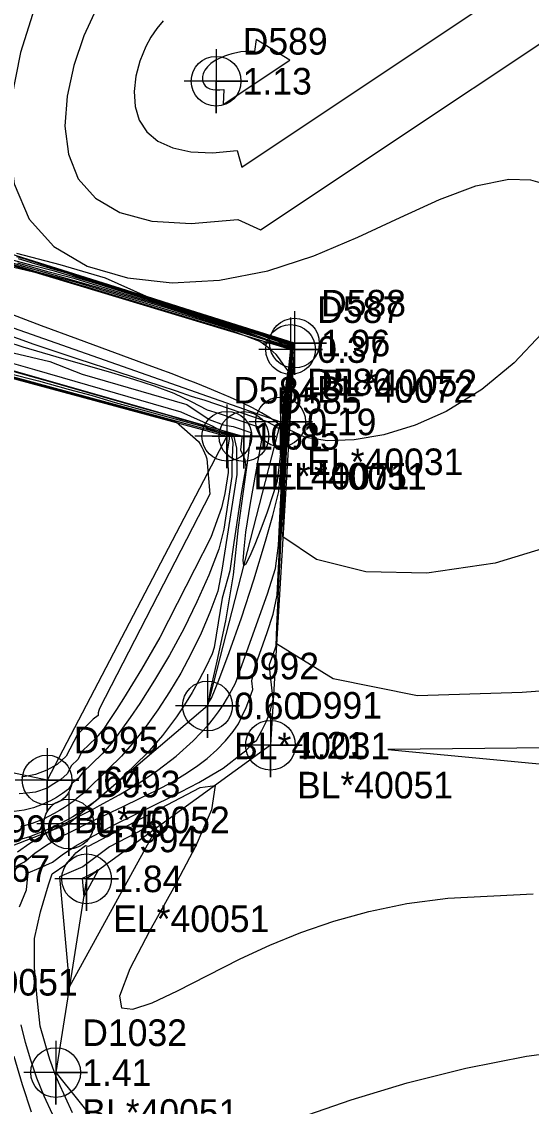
# Model space of a CAD drawing. Extents: x 2356077 to 2359823, y 225951 to 227822.
# Drawn here: x 2357246.2 to 2357294.1, y 226739.1 to 226841 of the extents above; entities that cross this region are included whole.
import ezdxf

# ---------------------------------------------------------------- set-up
doc = ezdxf.new("R2010")
doc.units = 0
for name, color, linetype in [('DTM Contours Major', 7, 'Continuous'), ('DTM Contours Minor', 7, 'Continuous'), ('Exist DTM Breakline', 7, 'Continuous'), ('Exist DTM Breakline Cogo Comment', 7, 'Continuous'), ('Exist DTM Breakline Cogo Elevation', 7, 'Continuous'), ('Exist DTM Breakline Cogo Number', 7, 'Continuous'), ('Exist DTM Breakline Cogo Point CELL', 7, 'Continuous'), ('Exist DTM Breakline Underwater', 7, 'Continuous'), ('Exist DTM Breakline Underwater Cogo Comment', 7, 'Continuous'), ('Exist DTM Breakline Underwater Cogo Elevation', 7, 'Continuous'), ('Exist DTM Breakline Underwater Cogo Number', 7, 'Continuous'), ('Exist DTM Breakline Underwater Cogo Point CELL', 7, 'Continuous'), ('Exist DTM Drainline', 7, 'Continuous'), ('Exist DTM Drainline Cogo Comment', 7, 'Continuous'), ('Exist DTM Drainline Cogo Elevation', 7, 'Continuous'), ('Exist DTM Drainline Cogo Number', 7, 'Continuous'), ('Exist DTM Drainline Cogo Point CELL', 7, 'Continuous'), ('Exist DTM Regular Point CELL', 7, 'Continuous'), ('Exist DTM Regular Point Cogo Elevation', 7, 'Continuous'), ('Exist DTM Regular Point Cogo Number', 7, 'Continuous')]:
    doc.layers.add(name, color=color, linetype=linetype)

msp = doc.modelspace()

# ---------------------------------------------------------------- linework, layer by layer
at = {"layer": 'DTM Contours Major'}
for points in [[(2357245.17, 226761.38), (2357246.44, 226762.04), (2357247.42, 226762.86), (2357248.52, 226763.61), (2357249.71, 226764.31), (2357250.98, 226764.93), (2357252.53, 226765.74), (2357254.12, 226766.49), (2357255.73, 226767.24), (2357257.33, 226768), (2357258.88, 226768.77), (2357260.36, 226769.56), (2357261.53, 226770.26), (2357262.63, 226770.99), (2357263.64, 226771.75), (2357264.55, 226772.55), (2357265.36, 226773.39), (2357266.07, 226774.29), (2357266.57, 226775), (2357266.93, 226775.75), (2357267.29, 226776.54), (2357267.62, 226777.36), (2357267.92, 226778.23), (2357267.82, 226779.05), (2357268.17, 226780.47), (2357269.28, 226783.58), (2357269.83, 226785.32), (2357270.21, 226787.1), (2357271.18, 226806.65), (2357271.23, 226807.34), (2357271.3, 226807.88), (2357271.36, 226808.56), (2357271.53, 226809.81), (2357271.53, 226810.41), (2357269.32, 226811.1), (2357267.47, 226811.77), (2357259.34, 226814.34), (2357256.62, 226815.18), (2357251.21, 226816.82), (2357248.64, 226817.5), (2357245.83, 226818.3)], [(2357245.43, 226808.13), (2357249.14, 226807.08), (2357256.93, 226804.85), (2357260.08, 226803.98), (2357261.05, 226803.68), (2357262.02, 226803.42), (2357263, 226803.14), (2357263.66, 226802.84), (2357266.11, 226802.14), (2357266.39, 226800.92), (2357266.41, 226798.45), (2357265.01, 226789.44), (2357264.64, 226787.46), (2357263.89, 226785.46), (2357263.05, 226783.51), (2357262.13, 226781.61), (2357261.15, 226779.77), (2357260.1, 226778.01), (2357259, 226776.33), (2357257.89, 226774.77), (2357256.74, 226773.31), (2357255.58, 226771.95), (2357254.33, 226770.73), (2357252.05, 226768.53), (2357251.6, 226768.16), (2357251.14, 226767.8), (2357250.67, 226767.46), (2357250.2, 226767.14), (2357249.73, 226766.84), (2357249.24, 226766.56), (2357248.23, 226766.05), (2357247.17, 226765.64), (2357246.06, 226765.31)], [(2357247.12, 226738.51), (2357246.25, 226741.06), (2357245.46, 226743.74)]]:
    msp.add_lwpolyline(points, dxfattribs=at)
at = {"layer": 'DTM Contours Minor'}
for points in [[(2357253.23, 226842.23), (2357252.04, 226839.67), (2357251.08, 226836.88), (2357250.45, 226834), (2357250.25, 226831.18), (2357250.57, 226828.54), (2357251.51, 226826.24), (2357253.12, 226824.4), (2357255.42, 226823.06), (2357258.42, 226822.25), (2357262.11, 226822.02), (2357266.5, 226822.4), (2357268.65, 226821.44), (2357308.56, 226848.03)], [(2357247.4, 226842.27), (2357246.07, 226838.09), (2357245.22, 226833.8), (2357244.97, 226829.61), (2357245.48, 226825.75), (2357246.87, 226822.43), (2357249.2, 226819.87), (2357252.35, 226818.03), (2357256.12, 226816.91), (2357260.33, 226816.46), (2357264.8, 226816.69), (2357269.34, 226817.57), (2357273.65, 226818.98), (2357277.81, 226820.74), (2357281.77, 226822.59), (2357285.48, 226824.29), (2357288.91, 226825.58), (2357292, 226826.21), (2357294.03, 226826.14), (2357295.8, 226825.63)], [(2357259.5, 226841.09), (2357258.89, 226840.35), (2357258.34, 226839.53), (2357257.85, 226838.65), (2357257.3, 226837.29), (2357256.92, 226835.87), (2357256.76, 226834.42), (2357256.85, 226833.03), (2357257.23, 226831.75), (2357257.94, 226830.63), (2357258.99, 226829.76), (2357260.39, 226829.13), (2357262.1, 226828.76), (2357264.13, 226828.68), (2357266.44, 226828.89), (2357266.89, 226827.32), (2357289.98, 226842.71)], [(2357271.4, 226837.39), (2357268.24, 226839.32), (2357268.09, 226838.2), (2357267.67, 226838.22), (2357267.24, 226838.2), (2357266.81, 226838.15), (2357266.38, 226838.07), (2357265.96, 226837.97), (2357265.55, 226837.85), (2357265.25, 226837.75), (2357264.97, 226837.63), (2357264.69, 226837.51), (2357264.44, 226837.37), (2357264.2, 226837.22), (2357263.98, 226837.07), (2357263.81, 226836.92), (2357263.66, 226836.76), (2357263.52, 226836.6), (2357263.41, 226836.43), (2357263.32, 226836.26), (2357263.25, 226836.09), (2357263.19, 226835.84), (2357263.18, 226835.6), (2357263.22, 226835.37), (2357263.31, 226835.16), (2357263.44, 226834.97), (2357263.63, 226834.82), (2357263.87, 226834.7), (2357264.15, 226834.62), (2357264.47, 226834.58), (2357264.82, 226834.58), (2357265.21, 226834.63), (2357265.13, 226833.21), (2357271.4, 226837.39)], [(2357245.38, 226809.88), (2357248.82, 226809.06), (2357251.86, 226807.87), (2357261.73, 226805.02), (2357263.81, 226803.61), (2357265.16, 226803.11), (2357266.06, 226802.95), (2357267.74, 226802.38), (2357267.5, 226800.22), (2357266.54, 226793.47), (2357266.09, 226789.02), (2357265.34, 226784.67), (2357264.54, 226780.88), (2357263.92, 226778.14), (2357263.72, 226776.93), (2357264.04, 226777.4), (2357264.74, 226779.09), (2357265.71, 226781.71), (2357266.85, 226784.97), (2357268.02, 226788.55), (2357269.13, 226792.18), (2357269.8, 226794.57), (2357270.38, 226796.84), (2357270.65, 226800.1), (2357270.89, 226805.05), (2357270.97, 226805.95), (2357271.31, 226808.43), (2357271.49, 226810.24), (2357269.76, 226810.78), (2357269.08, 226811.08), (2357266.93, 226811.76), (2357262.96, 226812.98), (2357251.25, 226816.51), (2357247.66, 226817.45), (2357242.79, 226818.92)], [(2357245.78, 226762.97), (2357246.95, 226763.8), (2357248.22, 226764.56), (2357249.56, 226765.28), (2357250.85, 226765.94), (2357252.16, 226766.61), (2357252.83, 226766.96), (2357253.51, 226767.31), (2357255.35, 226768.33), (2357257.19, 226769.44), (2357259, 226770.66), (2357260.72, 226771.97), (2357262.32, 226773.39), (2357263.74, 226774.91), (2357264.23, 226775.51), (2357264.69, 226776.13), (2357265.12, 226776.77), (2357265.53, 226777.44), (2357265.93, 226778.12), (2357266.3, 226778.83), (2357269.3, 226787.22), (2357270.05, 226789.6), (2357270.34, 226791.76), (2357271.04, 226805.87), (2357271.1, 226806.65), (2357271.28, 226807.95), (2357271.36, 226808.85), (2357271.46, 226809.6), (2357271.51, 226810.32), (2357270.09, 226810.77), (2357268.22, 226811.38), (2357267.32, 226811.73), (2357263.13, 226813.05), (2357259.78, 226814.09), (2357253.14, 226816.09), (2357250.15, 226816.93), (2357246.57, 226817.92), (2357243.15, 226818.96)], [(2357295.1, 226811.68), (2357292.5, 226808.92), (2357289.46, 226806.43), (2357286.12, 226804.36), (2357283.18, 226803.06), (2357280.25, 226802.17), (2357277.46, 226801.68), (2357274.96, 226801.6), (2357272.87, 226801.92), (2357271.35, 226802.64), (2357271.36, 226803.85), (2357271.61, 226808.83), (2357271.7, 226810.1), (2357271.77, 226810.63), (2357271.7, 226810.72), (2357267.01, 226812.2), (2357262.43, 226813.73), (2357257.91, 226815.16), (2357254.07, 226816.9), (2357249.79, 226818.13), (2357245.71, 226819.2)], [(2357297.39, 226792.13), (2357290.72, 226790.09), (2357284.3, 226789.15), (2357278.56, 226789.28), (2357273.9, 226790.44), (2357270.75, 226792.59), (2357270.84, 226795.34), (2357271.38, 226806.44), (2357271.55, 226809.26), (2357271.71, 226810.42), (2357271.63, 226810.65), (2357267.46, 226812.05), (2357247.95, 226818.21), (2357246.52, 226818.68), (2357245.71, 226818.91)], [(2357243.19, 226811.45), (2357246.28, 226810.44), (2357249.38, 226809.52), (2357254.62, 226808.03), (2357256.7, 226807.41), (2357258.65, 226806.76), (2357260.48, 226806.08), (2357262.11, 226805.29), (2357263.63, 226804.51), (2357264.67, 226804.2), (2357268.36, 226802.94), (2357268.74, 226801.65), (2357267.66, 226795.73), (2357267.24, 226793.02), (2357267.09, 226791.45), (2357267, 226790.35), (2357267.06, 226789.87), (2357267.29, 226790.07), (2357267.67, 226790.78), (2357268.15, 226791.9), (2357268.71, 226793.32), (2357269.29, 226794.93), (2357269.87, 226796.65), (2357270.25, 226797.84), (2357270.56, 226800.42), (2357270.74, 226804.22), (2357270.84, 226805.24), (2357271.24, 226808.17), (2357270.95, 226808.6), (2357270.35, 226809.44), (2357270.11, 226809.7), (2357269.85, 226809.96), (2357269.57, 226810.21), (2357269.26, 226810.45), (2357268.94, 226810.69), (2357268.59, 226810.93), (2357266.12, 226811.89), (2357252.31, 226816.04), (2357248.5, 226817.18), (2357244.26, 226818.19)], [(2357245.98, 226757.8), (2357246.65, 226759.41), (2357246.78, 226760.99), (2357247.84, 226761.45), (2357249.07, 226762.01), (2357250.11, 226762.79), (2357251.27, 226763.54), (2357252.53, 226764.27), (2357255, 226765.57), (2357260.3, 226768.17), (2357262.84, 226769.49), (2357265.12, 226770.85), (2357267, 226772.26), (2357267.22, 226772.46), (2357267.43, 226772.66), (2357267.63, 226772.86), (2357268.02, 226773.27), (2357268.27, 226773.45), (2357268.78, 226774.38), (2357269.24, 226775.31), (2357269.58, 226776.3), (2357269.83, 226777.33), (2357269.55, 226779.72), (2357269.5, 226780.58), (2357269.8, 226781.41), (2357270.11, 226782.34), (2357270.18, 226784.18), (2357271.32, 226807.41), (2357271.37, 226807.68), (2357271.37, 226808.39), (2357271.59, 226810.01), (2357271.55, 226810.49), (2357268.57, 226811.52), (2357253.47, 226816.28), (2357249.28, 226817.54), (2357247.16, 226818.08), (2357245.1, 226818.66)], [(2357302.93, 226778.66), (2357293.25, 226777.94), (2357283.4, 226777.64), (2357275.49, 226779.23), (2357270.15, 226782.53), (2357270.31, 226786.82), (2357271.16, 226804.07), (2357271.41, 226808.41), (2357271.65, 226810.22), (2357271.58, 226810.57), (2357268.24, 226811.72), (2357251.72, 226816.93), (2357250.35, 226817.38), (2357248.88, 226817.81), (2357247.42, 226818.25), (2357245.87, 226818.7)], [(2357243.22, 226812.15), (2357247.32, 226810.68), (2357251.47, 226809.3), (2357259.18, 226806.8), (2357260.7, 226806.3), (2357262.12, 226805.81), (2357262.76, 226805.61), (2357263.32, 226805.44), (2357269.18, 226803.44), (2357269.97, 226803.03), (2357269.96, 226802.9), (2357270.17, 226802.84), (2357270.26, 226802.83), (2357270.33, 226802.82), (2357270.4, 226802.81), (2357270.44, 226802.82), (2357270.47, 226802.83), (2357270.49, 226802.85), (2357270.51, 226802.88), (2357270.51, 226802.91), (2357270.5, 226802.95), (2357270.48, 226803.01), (2357270.43, 226803.07), (2357270.36, 226803.15), (2357270.26, 226803.25), (2357270.12, 226803.37), (2357269.96, 226803.49), (2357269.43, 226803.84), (2357268.73, 226804.24), (2357267.89, 226804.69), (2357266.92, 226805.16), (2357265.83, 226805.66), (2357264.64, 226806.18), (2357263.65, 226806.59), (2357262.6, 226807.01), (2357261.49, 226807.44), (2357260.33, 226807.89), (2357259.11, 226808.34), (2357257.82, 226808.82), (2357251.45, 226811.16), (2357248.06, 226812.42), (2357244.69, 226813.7)], [(2357243.39, 226809.42), (2357247.39, 226808.3), (2357261.15, 226804.33), (2357264.17, 226802.99), (2357264.54, 226802.75), (2357265.42, 226802.44), (2357266.54, 226802.11), (2357266.85, 226802.03), (2357266.88, 226801.88), (2357266.77, 226800.77), (2357267.16, 226799.84), (2357267.27, 226799.15), (2357266.82, 226796.66), (2357266.11, 226791.83), (2357265.75, 226789.38), (2357265.03, 226786.82), (2357264.3, 226782.19), (2357264.09, 226781.57), (2357263.5, 226780.33), (2357262.87, 226779.13), (2357262.21, 226777.95), (2357261.5, 226776.8), (2357260.74, 226775.67), (2357259.43, 226773.92), (2357258, 226772.24), (2357254.83, 226769.18), (2357253.22, 226767.8), (2357251.52, 226766.61), (2357250.98, 226766.27), (2357250.43, 226765.96), (2357249.88, 226765.66), (2357248.42, 226764.96), (2357246.92, 226764.39), (2357245.4, 226763.95)], [(2357241.84, 226808.52), (2357260.7, 226803.4), (2357262.81, 226801.53), (2357262.97, 226801.28), (2357263.12, 226801.01), (2357263.26, 226800.75), (2357263.38, 226800.47), (2357263.5, 226800.19), (2357263.6, 226799.9), (2357263.87, 226796.59), (2357253.51, 226776.45), (2357253.43, 226776.24), (2357253.37, 226776.03), (2357253.39, 226775.8), (2357252.9, 226775.43), (2357251.42, 226774), (2357250.36, 226771.96), (2357249.52, 226771.19), (2357248.54, 226770.64), (2357247.47, 226770.25), (2357247.16, 226770.17), (2357246.84, 226770.1), (2357246.51, 226770.04), (2357246.17, 226769.99)], [(2357243.76, 226808.07), (2357264.6, 226802.4), (2357265.7, 226802.09), (2357265.69, 226801.79), (2357265.5, 226800.63), (2357265.56, 226799.53), (2357265.6, 226798.64), (2357265.29, 226796.66), (2357264.97, 226795.29), (2357263.96, 226792.51), (2357262.45, 226789.5), (2357259.17, 226783.13), (2357257.46, 226780.13), (2357255.77, 226777.39), (2357255.11, 226776.36), (2357254.48, 226775.4), (2357253.88, 226774.5), (2357253.19, 226773.69), (2357251.88, 226772.43), (2357251.46, 226771.65), (2357250.86, 226771.1), (2357250.45, 226770.31), (2357249.86, 226769.78), (2357249.22, 226769.35), (2357248.59, 226768.96), (2357247.47, 226768.57), (2357246.67, 226768.5), (2357245.96, 226768.42)], [(2357244.92, 226807.97), (2357247.75, 226807.25), (2357250.55, 226806.45), (2357252.82, 226805.86), (2357254.99, 226805.2), (2357263.49, 226802.89), (2357263.56, 226802.79), (2357264.51, 226802.49), (2357265.89, 226802.09), (2357266.05, 226801.45), (2357265.94, 226799.35), (2357265.96, 226798.26), (2357265.19, 226793.3), (2357264.74, 226791.42), (2357263.79, 226788.97), (2357262.67, 226786.46), (2357261.42, 226783.94), (2357260.08, 226781.47), (2357258.69, 226779.11), (2357257.3, 226776.92), (2357256.4, 226775.59), (2357255.52, 226774.36), (2357254.65, 226773.22), (2357253.74, 226772.19), (2357251.89, 226770.41), (2357251.48, 226769.87), (2357250.94, 226769.43), (2357250.57, 226768.87), (2357250.02, 226768.46), (2357249.46, 226768.09), (2357248.88, 226767.76), (2357248.1, 226767.41), (2357247.28, 226767.12), (2357246.4, 226766.9), (2357245.46, 226766.75)], [(2357344.4, 226773.24), (2357280.62, 226772.59)], [(2357280.62, 226772.59), (2357336.59, 226767.29)], [(2357250.95, 226738.43), (2357249.63, 226741.33), (2357249.31, 226742.14), (2357249.01, 226742.95), (2357248.87, 226743.36), (2357248.73, 226743.76), (2357247.93, 226746.59), (2357247.64, 226749.25), (2357247.39, 226752.08), (2357247.38, 226754.81), (2357247.94, 226757.34), (2357248.71, 226759.87), (2357249.05, 226760.89), (2357250.33, 226761.78), (2357251.18, 226762.76), (2357251.26, 226762.88), (2357252.17, 226763.56), (2357252.47, 226763.5), (2357262.98, 226769.01), (2357264.37, 226769.21), (2357264.04, 226766.93), (2357262.56, 226763.54), (2357260.45, 226759.55), (2357258.21, 226755.52), (2357256.35, 226751.96), (2357255.37, 226749.4), (2357255.56, 226748.32), (2357256.63, 226748.18), (2357258.44, 226748.78), (2357260.83, 226749.9), (2357263.65, 226751.34), (2357266.74, 226752.9), (2357269.52, 226754.19), (2357272.44, 226755.38), (2357275.53, 226756.44), (2357278.83, 226757.36), (2357282.4, 226758.1), (2357286.28, 226758.62), (2357294.28, 226759.01)], [(2357249.74, 226760.63), (2357250.67, 226750.29), (2357258.88, 226765.22), (2357258.49, 226765.55), (2357254.45, 226763.43), (2357251.92, 226761.57), (2357249.74, 226760.63)], [(2357251.86, 226760.46), (2357252.02, 226758.74), (2357253.39, 226761.23), (2357253.38, 226761.26), (2357253.35, 226761.26), (2357253.3, 226761.24), (2357253.23, 226761.19), (2357253.15, 226761.13), (2357252.23, 226760.62), (2357251.86, 226760.46)], [(2357249.08, 226738.31), (2357248.3, 226740.01), (2357247.62, 226741.7), (2357247.03, 226743.38), (2357246.54, 226745.05), (2357246.12, 226746.72)], [(2357272.29, 226737.96), (2357277.16, 226739.67), (2357282.43, 226741.26), (2357287.96, 226742.65), (2357293.66, 226743.76), (2357299.38, 226744.51)]]:
    msp.add_lwpolyline(points, dxfattribs=at)
at = {"layer": 'Exist DTM Breakline'}
for points in [[(2357210.35, 226914.46), (2357201.62, 226892.13), (2357238.37, 226864.83), (2357223.94, 226826.63), (2357233.28, 226810.72), (2357265.48, 226802.03)], [(2357271.84, 226810.79), (2357233.69, 226822.75), (2357256.15, 226865.11), (2357219.6, 226886.5), (2357232.35, 226901.19)], [(2357271.84, 226810.79), (2357269.58, 226772.99), (2357252.29, 226760.43), (2357249.38, 226742.22)], [(2357265.48, 226802.03), (2357248.57, 226769.72), (2357215.71, 226776.62), (2357199.96, 226753.24), (2357185.71, 226723.56)], [(2357249.38, 226742.22), (2357281.74, 226701.95), (2357270.97, 226680.54), (2357283.19, 226665.62), (2357270.35, 226637.6), (2357246.32, 226638.79), (2357228.89, 226630.75)]]:
    msp.add_lwpolyline(points, dxfattribs=at)
at = {"layer": 'Exist DTM Breakline Cogo Point CELL'}
for points in [[(2357271.84, 226813.79), (2357271.84, 226807.79), (2357271.84, 226810.79), (2357274.84, 226810.79), (2357268.84, 226810.79)], [(2357267.09, 226805.01), (2357267.09, 226799.01), (2357267.09, 226802.01), (2357270.09, 226802.01), (2357264.09, 226802.01)], [(2357269.58, 226775.99), (2357269.58, 226769.99), (2357269.58, 226772.99), (2357272.58, 226772.99), (2357266.58, 226772.99)], [(2357248.57, 226772.72), (2357248.57, 226766.72), (2357248.57, 226769.72), (2357251.57, 226769.72), (2357245.57, 226769.72)], [(2357252.29, 226763.43), (2357252.29, 226757.43), (2357252.29, 226760.43), (2357255.29, 226760.43), (2357249.29, 226760.43)], [(2357249.38, 226745.22), (2357249.38, 226739.22), (2357249.38, 226742.22), (2357252.38, 226742.22), (2357246.38, 226742.22)]]:
    msp.add_lwpolyline(points, dxfattribs=at)
for centre in [(2357271.84, 226810.79), (2357267.09, 226802.01), (2357269.58, 226772.99), (2357248.57, 226769.72), (2357252.29, 226760.43), (2357249.38, 226742.22)]:
    msp.add_circle(centre, 2.34, dxfattribs=at)
at = {"layer": 'Exist DTM Breakline Underwater'}
for points in [[(2357211.57, 226913.68), (2357202.73, 226893.21), (2357241.45, 226865.04), (2357224.72, 226826.21), (2357233.45, 226811.6), (2357267.09, 226802.01)], [(2357271.48, 226810.18), (2357230.99, 226822.36), (2357255.15, 226864.97), (2357217.98, 226886.04), (2357231.07, 226902.17)]]:
    msp.add_lwpolyline(points, dxfattribs=at)
at = {"layer": 'Exist DTM Breakline Underwater Cogo Point CELL'}
for points in [[(2357271.48, 226813.18), (2357271.48, 226807.18), (2357271.48, 226810.18), (2357274.48, 226810.18), (2357268.48, 226810.18)], [(2357265.48, 226805.03), (2357265.48, 226799.03), (2357265.48, 226802.03), (2357268.48, 226802.03), (2357262.48, 226802.03)]]:
    msp.add_lwpolyline(points, dxfattribs=at)
for centre in [(2357271.48, 226810.18), (2357265.48, 226802.03)]:
    msp.add_circle(centre, 2.34, dxfattribs=at)
at = {"layer": 'Exist DTM Drainline'}
for points in [[(2357222.63, 226906.59), (2357214.8, 226885.75), (2357245.44, 226865.87), (2357226.11, 226826.22), (2357233.92, 226816.22), (2357270.54, 226803.38)], [(2357270.54, 226803.38), (2357263.66, 226776.68)], [(2357263.66, 226776.68), (2357250.62, 226765.59), (2357239.84, 226761.4), (2357218.65, 226771.02), (2357205.09, 226748.5), (2357204.02, 226726.02)]]:
    msp.add_lwpolyline(points, dxfattribs=at)
at = {"layer": 'Exist DTM Drainline Cogo Point CELL'}
for points in [[(2357270.54, 226806.38), (2357270.54, 226800.38), (2357270.54, 226803.38), (2357273.54, 226803.38), (2357267.54, 226803.38)], [(2357263.66, 226779.68), (2357263.66, 226773.68), (2357263.66, 226776.68), (2357266.66, 226776.68), (2357260.66, 226776.68)], [(2357250.62, 226768.59), (2357250.62, 226762.59), (2357250.62, 226765.59), (2357253.62, 226765.59), (2357247.62, 226765.59)]]:
    msp.add_lwpolyline(points, dxfattribs=at)
for centre in [(2357270.54, 226803.38), (2357263.66, 226776.68), (2357250.62, 226765.59)]:
    msp.add_circle(centre, 2.34, dxfattribs=at)
at = {"layer": 'Exist DTM Regular Point CELL'}
msp.add_lwpolyline([(2357264.47, 226838.4), (2357264.47, 226832.4), (2357264.47, 226835.4), (2357267.47, 226835.4), (2357261.47, 226835.4)], dxfattribs=at)
msp.add_circle((2357264.47, 226835.4), 2.34, dxfattribs=at)

# ---------------------------------------------------------------- texts
at = {"layer": 'Exist DTM Breakline Cogo Comment'}
for s, p in [('BL*40052', (2357274.34, 226805.79)), ('EL*40051', (2357269.59, 226797.01)), ('BL*40051', (2357272.08, 226767.99)), ('BL*40052', (2357251.07, 226764.72)), ('EL*40051', (2357254.79, 226755.43)), ('BL*40051', (2357236.76, 226749.46)), ('BL*40051', (2357251.88, 226737.22))]:
    msp.add_text(s, height=2.5, dxfattribs=at).set_placement(p)
at = {"layer": 'Exist DTM Breakline Cogo Elevation'}
for s, p in [('1.96', (2357274.34, 226809.54)), ('0.85', (2357269.59, 226800.76)), ('1.21', (2357272.08, 226771.74)), ('1.64', (2357251.07, 226768.47)), ('1.84', (2357254.79, 226759.18)), ('1.41', (2357251.88, 226740.97))]:
    msp.add_text(s, height=2.5, dxfattribs=at).set_placement(p)
at = {"layer": 'Exist DTM Breakline Cogo Number'}
for s, p in [('D588', (2357274.34, 226813.29)), ('D585', (2357270.16, 226804.14)), ('D991', (2357272.08, 226775.49)), ('D995', (2357251.07, 226772.22)), ('D994', (2357254.79, 226762.93)), ('D1032', (2357251.88, 226744.72))]:
    msp.add_text(s, height=2.5, dxfattribs=at).set_placement(p)
at = {"layer": 'Exist DTM Breakline Underwater Cogo Comment'}
for s, p in [('BL*40072', (2357273.98, 226805.18)), ('EL*40071', (2357267.98, 226797.03))]:
    msp.add_text(s, height=2.5, dxfattribs=at).set_placement(p)
at = {"layer": 'Exist DTM Breakline Underwater Cogo Elevation'}
for s, p in [('0.37', (2357273.98, 226808.93)), ('1.61', (2357267.98, 226800.78))]:
    msp.add_text(s, height=2.5, dxfattribs=at).set_placement(p)
at = {"layer": 'Exist DTM Breakline Underwater Cogo Number'}
for s, p in [('D587', (2357273.98, 226812.68)), ('D584', (2357266.09, 226805.11))]:
    msp.add_text(s, height=2.5, dxfattribs=at).set_placement(p)
at = {"layer": 'Exist DTM Drainline Cogo Comment'}
for s, p in [('EL*40031', (2357273.04, 226798.38)), ('BL*40031', (2357266.16, 226771.68))]:
    msp.add_text(s, height=2.5, dxfattribs=at).set_placement(p)
at = {"layer": 'Exist DTM Drainline Cogo Elevation'}
for s, p in [('0.19', (2357273.04, 226802.13)), ('0.60', (2357266.16, 226775.43)), ('0.75', (2357253.12, 226764.34)), ('0.67', (2357242.34, 226760.15))]:
    msp.add_text(s, height=2.5, dxfattribs=at).set_placement(p)
at = {"layer": 'Exist DTM Drainline Cogo Number'}
for s, p in [('D586', (2357273.04, 226805.88)), ('D992', (2357266.16, 226779.18)), ('D993', (2357253.12, 226768.09)), ('D996', (2357242.34, 226763.9))]:
    msp.add_text(s, height=2.5, dxfattribs=at).set_placement(p)
at = {"layer": 'Exist DTM Regular Point Cogo Elevation'}
msp.add_text('1.13', height=2.5, dxfattribs=at).set_placement((2357266.97, 226834.15))
at = {"layer": 'Exist DTM Regular Point Cogo Number'}
msp.add_text('D589', height=2.5, dxfattribs=at).set_placement((2357266.97, 226837.9))

doc.saveas('drawing.dxf')
